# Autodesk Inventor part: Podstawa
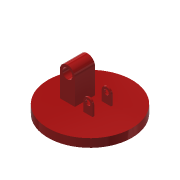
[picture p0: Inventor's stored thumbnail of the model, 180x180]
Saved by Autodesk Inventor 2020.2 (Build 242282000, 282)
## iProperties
Created: 2005-10
Part Number: Podstawa
Document SubType Name: Modeling
Designer: F.Stasiak
Density: 1 g/cm^3
Material: Ogólny
Appearance: Gładkie — czerwone
Manager: www.cadconsulting.pl
Company: Fabian Stasiak CAD Consulting
Author: F.Stasiak
Subject: Zbiór ćwiczeń. Autodesk Inventor 2020. Kurs podstawowy
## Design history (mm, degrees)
sketch "Szkic1"
  geometry: C1 r 500 at (0, 0); 1 further point
  constraints: 1 centre point, 1 coincident
  dimensions: "d0" = 1000 diameter of C1
extrude "Wyciągnięcie proste1" new body sketch "Szkic1" distance "d1" = 100; taper "d2" = 0 deg
sketch "Szkic2"
  geometry: L1 (-500, 100)-(500, 100) reference; L2 (240, 100)-(240, 400); L3 (60, 400)-(60, 100); L4 (240, 100)-(60, 100); A1 r 90 centre (150, 400) between (240, 400) and (60, 400); 1 further point
  constraints: 6 end point, 3 perpendicular, 2 point on circle, 2 point on line, 2 tangent, 1 centre point
  dimensions: "d3" = 90 radius of A1; "d4" = 300 distance of L3.start L3.end; "d14" = 60 distance from line of point (0, 0) L3
extrude "Wyciągnięcie proste2" join sketch "Szkic2" stored distance "d5" = 240; taper "d6" = 0 deg
sketch "Szkic3"
  geometry: L1 (-240, 100)-(-240, 400) reference; L2 (-60, 100)-(-240, 100) reference; L3 (-60, 400)-(-60, 100) reference; A1 r 90 centre (-150, 400) between (-60, 400) and (-240, 400) reference
hole "Otwór1" sketch "Szkic3" at (-150, 400) diameter "d7" = 120; stored, may be unused: countersink angle "d11" = 90 deg, drill point angle "d13" = 118 deg; dims "d8" = 6, "d9" = 4, "d10" = 2, "d12" = 8
sketch "Szkic4"
  geometry: L1 (-500, 100)-(500, 100) reference; L2 (40, 100)-(150, 100); L3 (150, 220)-(150, 100); L4 (40, 220)-(40, 100); L5 (-60, 400)-(-60, 100) reference; C1 r 30 at (95, 220); A1 r 55 centre (95, 220) between (150, 220) and (40, 220)
  constraints: 6 end point, 2 centre point, 2 point on circle, 2 point on line, 2 tangent, 1 coincident, 1 parallel, 1 perpendicular
  dimensions: "d15" = 55 radius of A1; "d16" = 120 distance of L3.start L2.end; "d17" = 100 distance between parallel lines of L5 L4; "d18" = 60 diameter of C1
extrude "Wyciągnięcie proste3" join sketch "Szkic4" distance "d19" = 20; taper "d20" = 0 deg
mirror "Lustro1"
node "Bryła1"
node "Korpusy bryłowe"
node "Korpusy powierzchniowe"
node "Pętla rzutowana1"
